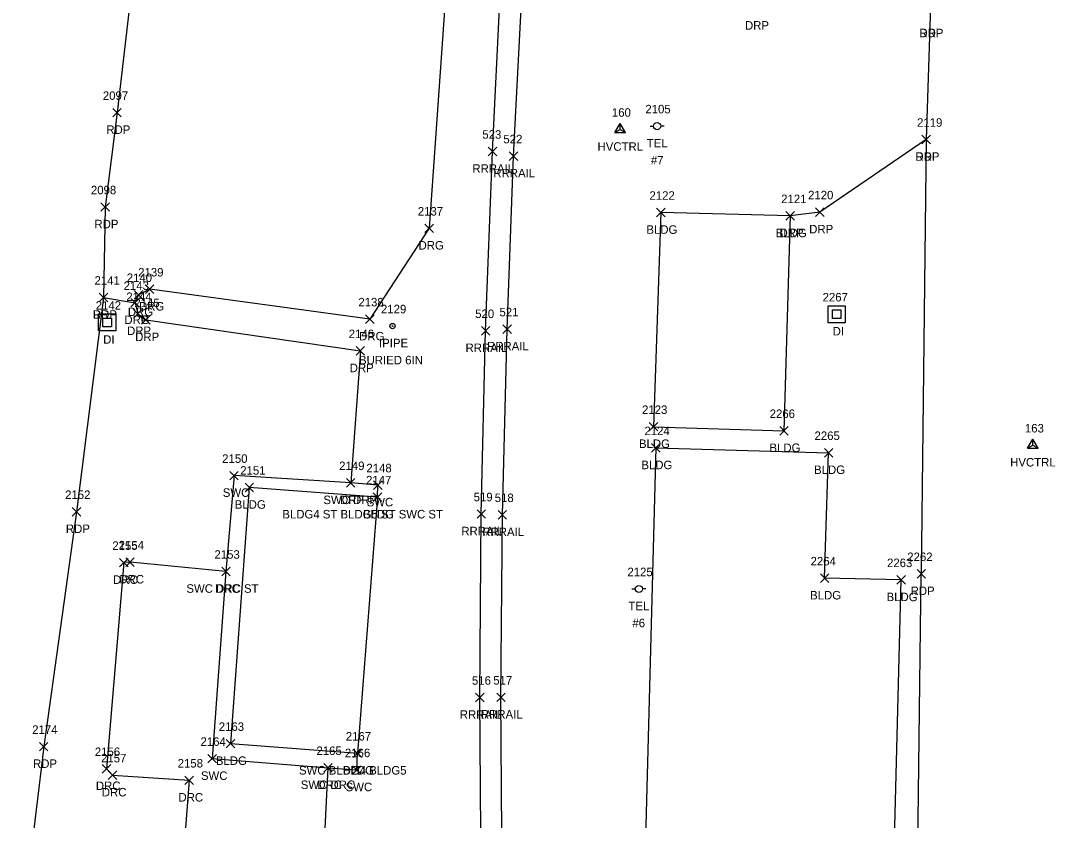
# Model space of a CAD drawing. Extents: x 1767353 to 1772625, y 740790 to 747702.
# Drawn here: x 1770045.2 to 1770288.3, y 741351 to 741538.9 of the extents above; entities that cross this region are included whole.
import ezdxf

# ---------------------------------------------------------------- set-up
doc = ezdxf.new("R2010")
doc.units = 0
for name, color, linetype in [('C_A', 7, 'Continuous'), ('C_I', 7, 'Continuous'), ('CPSM', 7, 'Continuous'), ('D_A', 7, 'Continuous'), ('D_I', 7, 'Continuous'), ('DS', 7, 'Continuous'), ('L_A', 7, 'Continuous'), ('L_I', 7, 'Continuous'), ('L_TIC', 7, 'Continuous'), ('LBC', 7, 'Continuous'), ('M_A', 7, 'Continuous'), ('M_C', 7, 'Continuous'), ('M_I', 7, 'Continuous'), ('MPIP', 7, 'Continuous'), ('P_A', 7, 'Continuous'), ('P_I', 7, 'Continuous'), ('P_TIC', 7, 'Continuous'), ('PET', 7, 'Continuous'), ('R_A', 7, 'Continuous'), ('R_I', 7, 'Continuous'), ('R_TIC', 7, 'Continuous'), ('RDG', 7, 'Continuous'), ('RDP', 7, 'Continuous'), ('RR', 7, 'Continuous'), ('RSW', 7, 'Continuous'), ('U_A', 7, 'Continuous'), ('U_C', 7, 'Continuous'), ('U_I', 7, 'Continuous'), ('UP', 7, 'Continuous')]:
    doc.layers.add(name, color=color, linetype=linetype)

msp = doc.modelspace()

# ---------------------------------------------------------------- linework, layer by layer
at = {"layer": 'CPSM'}
for p, q in [((1770184.78, 741512.6), (1770186.03, 741514.77)), ((1770184.78, 741512.6), (1770186.04, 741513.33)), ((1770187.28, 741512.6), (1770186.03, 741514.77)), ((1770186.04, 741513.33), (1770186.03, 741514.77)), ((1770186.04, 741513.33), (1770186.04, 741513.33)), ((1770186.04, 741513.33), (1770187.28, 741512.6)), ((1770184.78, 741512.6), (1770187.28, 741512.6)), ((1770281.75, 741438.4), (1770283, 741440.56)), ((1770284.25, 741438.4), (1770283, 741440.56)), ((1770283, 741439.12), (1770283, 741440.56)), ((1770281.75, 741438.4), (1770283, 741439.12)), ((1770281.75, 741438.4), (1770284.25, 741438.4)), ((1770283, 741439.12), (1770283, 741439.12)), ((1770283, 741439.12), (1770284.25, 741438.4))]:
    msp.add_line(p, q, dxfattribs=at)
at = {"layer": 'DS'}
for p, q in [((1770234.92, 741471.91), (1770238.92, 741471.91)), ((1770234.92, 741467.91), (1770234.92, 741471.91)), ((1770238.92, 741471.91), (1770238.92, 741467.91)), ((1770063.5, 741469.97), (1770067.5, 741469.97)), ((1770063.5, 741465.97), (1770063.5, 741469.97)), ((1770067.5, 741469.97), (1770067.5, 741465.97)), ((1770235.92, 741468.91), (1770235.92, 741470.91)), ((1770235.92, 741470.91), (1770237.92, 741470.91)), ((1770236.93, 741469.91), (1770236.93, 741469.91)), ((1770236.93, 741469.91), (1770236.93, 741469.91)), ((1770237.92, 741470.91), (1770237.92, 741468.91)), ((1770064.5, 741466.97), (1770064.5, 741468.97)), ((1770064.5, 741468.97), (1770066.5, 741468.97)), ((1770066.5, 741466.97), (1770064.5, 741466.97)), ((1770065.5, 741467.97), (1770065.5, 741467.97)), ((1770065.5, 741467.97), (1770065.5, 741467.97)), ((1770066.5, 741468.97), (1770066.5, 741466.97)), ((1770238.92, 741467.91), (1770234.92, 741467.91)), ((1770237.92, 741468.91), (1770235.92, 741468.91)), ((1770067.5, 741465.97), (1770063.5, 741465.97))]:
    msp.add_line(p, q, dxfattribs=at)
at = {"layer": 'L_TIC'}
for points in [[(1770194.62, 741492.81), (1770196.62, 741494.81)], [(1770196.62, 741492.81), (1770194.62, 741494.81)], [(1770225.01, 741492.02), (1770227.01, 741494.02)], [(1770227.01, 741492.02), (1770225.01, 741494.02)], [(1770225.01, 741492.02), (1770227.01, 741494.02)], [(1770227.01, 741492.02), (1770225.01, 741494.02)], [(1770192.88, 741442.47), (1770194.88, 741444.47)], [(1770194.88, 741442.47), (1770192.88, 741444.47)], [(1770223.54, 741441.52), (1770225.54, 741443.52)], [(1770225.54, 741441.52), (1770223.54, 741443.52)], [(1770223.54, 741441.52), (1770225.54, 741443.52)], [(1770225.54, 741441.52), (1770223.54, 741443.52)], [(1770193.44, 741437.49), (1770195.44, 741439.49)], [(1770195.44, 741437.49), (1770193.44, 741439.49)], [(1770193.44, 741437.49), (1770195.44, 741439.49)], [(1770195.44, 741437.49), (1770193.44, 741439.49)], [(1770234.03, 741436.35), (1770236.03, 741438.35)], [(1770236.03, 741436.35), (1770234.03, 741438.35)], [(1770234.03, 741436.35), (1770236.03, 741438.35)], [(1770236.03, 741436.35), (1770234.03, 741438.35)], [(1770097.89, 741428.19), (1770099.89, 741430.19)], [(1770099.89, 741428.19), (1770097.89, 741430.19)], [(1770128.02, 741425.91), (1770130.02, 741427.91)], [(1770130.02, 741425.91), (1770128.02, 741427.91)], [(1770128.02, 741425.91), (1770130.02, 741427.91)], [(1770130.02, 741425.91), (1770128.02, 741427.91)], [(1770233.09, 741406.87), (1770235.09, 741408.87)], [(1770235.09, 741406.87), (1770233.09, 741408.87)], [(1770251.07, 741406.47), (1770253.07, 741408.47)], [(1770253.07, 741406.47), (1770251.07, 741408.47)], [(1770093.46, 741367.98), (1770095.46, 741369.98)], [(1770095.46, 741367.98), (1770093.46, 741369.98)], [(1770123.31, 741365.71), (1770125.31, 741367.71)], [(1770125.31, 741365.71), (1770123.31, 741367.71)], [(1770123.31, 741365.71), (1770125.31, 741367.71)], [(1770125.31, 741365.71), (1770123.31, 741367.71)]]:
    msp.add_lwpolyline(points, dxfattribs=at)
at = {"layer": 'LBC'}
for points in [[(1770226.01, 741493.02), (1770195.62, 741493.81), (1770193.88, 741443.47), (1770224.54, 741442.52)], [(1770226.01, 741493.02), (1770224.54, 741442.52)], [(1770194.44, 741438.49), (1770191.02, 741308.31), (1770207.19, 741307.57), (1770249.47, 741306.66), (1770252.07, 741407.47), (1770234.09, 741407.87), (1770235.03, 741437.35)], [(1770194.44, 741438.49), (1770235.03, 741437.35)], [(1770129.02, 741426.91), (1770098.89, 741429.19), (1770094.46, 741368.98), (1770124.31, 741366.71)], [(1770129.02, 741426.91), (1770124.31, 741366.71)]]:
    msp.add_lwpolyline(points, dxfattribs=at)
at = {"layer": 'MPIP'}
for radius in [0.625, 0.0833]:
    msp.add_circle((1770132.54, 741467.13), radius, dxfattribs=at)
at = {"layer": 'P_TIC'}
for points in [[(1770066.82, 741516.29), (1770068.82, 741518.29)], [(1770068.82, 741516.29), (1770066.82, 741518.29)], [(1770256.94, 741509.97), (1770258.94, 741511.97)], [(1770258.94, 741509.97), (1770256.94, 741511.97)], [(1770064.02, 741494.1), (1770066.02, 741496.1)], [(1770066.02, 741494.1), (1770064.02, 741496.1)], [(1770063.65, 741472.85), (1770065.65, 741474.85)], [(1770065.65, 741472.85), (1770063.65, 741474.85)], [(1770057.3, 741422.48), (1770059.3, 741424.48)], [(1770059.3, 741422.48), (1770057.3, 741424.48)], [(1770255.82, 741407.89), (1770257.82, 741409.89)], [(1770257.82, 741407.89), (1770255.82, 741409.89)], [(1770255.82, 741407.89), (1770257.82, 741409.89)], [(1770257.82, 741407.89), (1770255.82, 741409.89)], [(1770049.58, 741367.28), (1770051.58, 741369.28)], [(1770051.58, 741367.28), (1770049.58, 741369.28)]]:
    msp.add_lwpolyline(points, dxfattribs=at)
at = {"layer": 'PET'}
for points in [[(1770086.36, 741896.23), (1770087.49, 741787.65), (1770087.53, 741783.15), (1770087.13, 741775.79), (1770085.91, 741755.24), (1770081.77, 741704.72), (1770080.78, 741668.58), (1770077.45, 741606.56), (1770073.71, 741567.99), (1770067.82, 741517.29), (1770065.02, 741495.1), (1770064.65, 741473.85), (1770058.3, 741423.48), (1770050.58, 741368.28), (1770045.18, 741323.67)], [(1770259.69, 741610.34), (1770259.04, 741577.82), (1770258.88, 741540.01), (1770257.94, 741510.97), (1770256.82, 741408.89)], [(1770255.54, 741305.89), (1770256.82, 741408.89)]]:
    msp.add_lwpolyline(points, dxfattribs=at)
at = {"layer": 'R_TIC'}
for points in [[(1770256.94, 741509.97), (1770258.94, 741511.97)], [(1770258.94, 741509.97), (1770256.94, 741511.97)], [(1770155.03, 741507.16), (1770157.03, 741509.16)], [(1770157.03, 741507.16), (1770155.03, 741509.16)], [(1770159.97, 741506.07), (1770161.97, 741508.07)], [(1770161.97, 741506.07), (1770159.97, 741508.07)], [(1770225.01, 741492.02), (1770227.01, 741494.02)], [(1770227.01, 741492.02), (1770225.01, 741494.02)], [(1770231.98, 741492.91), (1770233.98, 741494.91)], [(1770233.98, 741492.91), (1770231.98, 741494.91)], [(1770140.18, 741489.11), (1770142.18, 741491.11)], [(1770142.18, 741489.11), (1770140.18, 741491.11)], [(1770074.49, 741474.78), (1770076.49, 741476.78)], [(1770076.49, 741474.78), (1770074.49, 741476.78)], [(1770063.65, 741472.85), (1770065.65, 741474.85)], [(1770065.65, 741472.85), (1770063.65, 741474.85)], [(1770071.87, 741473.48), (1770073.87, 741475.48)], [(1770073.87, 741473.48), (1770071.87, 741475.48)], [(1770071.05, 741471.61), (1770073.05, 741473.61)], [(1770073.05, 741471.61), (1770071.05, 741473.61)], [(1770071.05, 741471.61), (1770073.05, 741473.61)], [(1770073.05, 741471.61), (1770071.05, 741473.61)], [(1770071.68, 741469.01), (1770073.68, 741471.01)], [(1770073.68, 741469.01), (1770071.68, 741471.01)], [(1770073.59, 741467.58), (1770075.59, 741469.58)], [(1770075.59, 741467.58), (1770073.59, 741469.58)], [(1770126.23, 741467.75), (1770128.23, 741469.75)], [(1770128.23, 741467.75), (1770126.23, 741469.75)], [(1770153.43, 741465.02), (1770155.43, 741467.02)], [(1770155.43, 741465.02), (1770153.43, 741467.02)], [(1770158.48, 741465.41), (1770160.48, 741467.41)], [(1770160.48, 741465.41), (1770158.48, 741467.41)], [(1770124, 741460.29), (1770126, 741462.29)], [(1770126, 741460.29), (1770124, 741462.29)], [(1770094.31, 741430.98), (1770096.31, 741432.98)], [(1770096.31, 741430.98), (1770094.31, 741432.98)], [(1770121.72, 741429.28), (1770123.72, 741431.28)], [(1770123.72, 741429.28), (1770121.72, 741431.28)], [(1770121.72, 741429.28), (1770123.72, 741431.28)], [(1770123.72, 741429.28), (1770121.72, 741431.28)], [(1770128.11, 741428.75), (1770130.11, 741430.75)], [(1770130.11, 741428.75), (1770128.11, 741430.75)], [(1770128.02, 741425.91), (1770130.02, 741427.91)], [(1770130.02, 741425.91), (1770128.02, 741427.91)], [(1770152.42, 741421.94), (1770154.42, 741423.94)], [(1770154.42, 741421.94), (1770152.42, 741423.94)], [(1770157.37, 741421.76), (1770159.37, 741423.76)], [(1770159.37, 741421.76), (1770157.37, 741423.76)], [(1770068.4, 741410.52), (1770070.4, 741412.52)], [(1770070.4, 741410.52), (1770068.4, 741412.52)], [(1770069.88, 741410.63), (1770071.88, 741412.63)], [(1770071.88, 741410.63), (1770069.88, 741412.63)], [(1770092.41, 741408.44), (1770094.41, 741410.44)], [(1770094.41, 741408.44), (1770092.41, 741410.44)], [(1770092.41, 741408.44), (1770094.41, 741410.44)], [(1770094.41, 741408.44), (1770092.41, 741410.44)], [(1770152.07, 741378.82), (1770154.07, 741380.82)], [(1770154.07, 741378.82), (1770152.07, 741380.82)], [(1770157.03, 741378.87), (1770159.03, 741380.87)], [(1770159.03, 741378.87), (1770157.03, 741380.87)], [(1770123.31, 741365.71), (1770125.31, 741367.71)], [(1770125.31, 741365.71), (1770123.31, 741367.71)], [(1770089.17, 741364.46), (1770091.17, 741366.46)], [(1770091.17, 741364.46), (1770089.17, 741366.46)], [(1770064.35, 741362.07), (1770066.35, 741364.07)], [(1770066.35, 741362.07), (1770064.35, 741364.07)], [(1770065.76, 741360.57), (1770067.76, 741362.57)], [(1770067.76, 741360.57), (1770065.76, 741362.57)], [(1770116.41, 741362.31), (1770118.41, 741364.31)], [(1770118.41, 741362.31), (1770116.41, 741364.31)], [(1770116.41, 741362.31), (1770118.41, 741364.31)], [(1770118.41, 741362.31), (1770116.41, 741364.31)], [(1770123.17, 741361.8), (1770125.17, 741363.8)], [(1770125.17, 741361.8), (1770123.17, 741363.8)], [(1770083.76, 741359.37), (1770085.76, 741361.37)], [(1770085.76, 741359.37), (1770083.76, 741361.37)]]:
    msp.add_lwpolyline(points, dxfattribs=at)
at = {"layer": 'RDG'}
msp.add_lwpolyline([(1770133.81, 741561.26), (1770145.92, 741558.06), (1770141.18, 741490.11), (1770127.23, 741468.75), (1770075.49, 741475.78), (1770072.87, 741474.48), (1770072.05, 741472.61)], dxfattribs=at)
at = {"layer": 'RDP'}
for points in [[(1770257.94, 741510.97), (1770232.98, 741493.91), (1770226.01, 741493.02)], [(1770064.65, 741473.85), (1770072.05, 741472.61), (1770072.68, 741470.01), (1770074.59, 741468.58), (1770125, 741461.29), (1770122.72, 741430.28)], [(1770093.41, 741409.44), (1770070.88, 741411.63), (1770069.4, 741411.52), (1770065.35, 741363.07), (1770066.76, 741361.57), (1770084.76, 741360.37), (1770082.95, 741336.98), (1770084.22, 741335.12), (1770115.82, 741330.18), (1770117.41, 741363.31)]]:
    msp.add_lwpolyline(points, dxfattribs=at)
at = {"layer": 'RR'}
for points in [[(1770158.18, 741192.17), (1770156.33, 741234.55), (1770154.66, 741279.77), (1770153.5, 741326.69), (1770153.07, 741379.82), (1770153.42, 741422.94), (1770154.43, 741466.02), (1770156.03, 741508.16), (1770157.87, 741545.07), (1770160.69, 741586.39), (1770163.59, 741622.82), (1770166.84, 741658.9), (1770171.01, 741697.88), (1770175.49, 741734.8), (1770180.59, 741775.05), (1770185.91, 741810.5), (1770192.47, 741851.32), (1770197.89, 741882.78), (1770201.13, 741901.96), (1770208.66, 741941.8), (1770211.54, 741956.24), (1770217.02, 741983.21), (1770222.11, 742006.18)], [(1770163.08, 741192.31), (1770161.21, 741234.64), (1770159.62, 741280.6), (1770158.4, 741326.37), (1770158.03, 741379.87), (1770158.37, 741422.76), (1770159.48, 741466.41), (1770160.97, 741507.07), (1770162.92, 741544.79), (1770165.6, 741585.33), (1770168.59, 741623.26), (1770171.89, 741657.97), (1770175.98, 741697.29), (1770180.38, 741733.87), (1770185.58, 741774.59), (1770190.55, 741808.84), (1770197.31, 741850.84), (1770202.43, 741880.83), (1770205.99, 741900.79), (1770213.55, 741940.61), (1770216.39, 741955.4), (1770221.78, 741982.04), (1770226.9, 742005.14)]]:
    msp.add_lwpolyline(points, dxfattribs=at)
at = {"layer": 'RSW'}
msp.add_lwpolyline([(1770129.02, 741426.91), (1770129.11, 741429.75), (1770122.72, 741430.28), (1770095.31, 741431.98), (1770093.41, 741409.44), (1770090.17, 741365.46), (1770117.41, 741363.31), (1770124.17, 741362.8), (1770124.31, 741366.71)], dxfattribs=at)
at = {"layer": 'UP'}
for p, q in [((1770193.08, 741514.12), (1770193.9, 741514.12)), ((1770194.74, 741514.12), (1770194.74, 741514.12)), ((1770196.4, 741514.12), (1770195.57, 741514.12)), ((1770195.57, 741514.12), (1770195.57, 741514.12)), ((1770196.4, 741514.12), (1770196.4, 741514.12)), ((1770188.79, 741405.33), (1770189.61, 741405.33)), ((1770190.45, 741405.34), (1770190.45, 741405.34)), ((1770192.11, 741405.34), (1770191.28, 741405.34)), ((1770191.28, 741405.34), (1770191.28, 741405.34)), ((1770192.11, 741405.34), (1770192.11, 741405.34))]:
    msp.add_line(p, q, dxfattribs=at)
for centre in [(1770194.74, 741514.12), (1770190.45, 741405.34)]:
    msp.add_circle(centre, 0.833, dxfattribs=at)

# ---------------------------------------------------------------- texts
at = {"layer": 'C_A'}
for p in [(1770180.73, 741508.33), (1770277.7, 741434.12)]:
    msp.add_text('HVCTRL', height=2, dxfattribs=at).set_placement(p)
at = {"layer": 'C_I'}
for s, p in [('160', (1770184.11, 741516.33)), ('163', (1770281.16, 741442.12))]:
    msp.add_text(s, height=2, dxfattribs=at).set_placement(p)
at = {"layer": 'D_A'}
for p in [(1770235.98, 741464.91), (1770064.56, 741462.97)]:
    msp.add_text('DI', height=2, dxfattribs=at).set_placement(p)
at = {"layer": 'D_I'}
for s, p in [('2267', (1770233.62, 741472.91)), ('2142', (1770062.81, 741470.97))]:
    msp.add_text(s, height=2, dxfattribs=at).set_placement(p)
at = {"layer": 'L_A'}
for p in [(1770192.21, 741488.81), (1770222.61, 741488.02), (1770222.61, 741488.02), (1770190.47, 741438.47), (1770221.13, 741437.52), (1770221.13, 741437.52), (1770191.03, 741433.49), (1770191.03, 741433.49), (1770231.62, 741432.35), (1770231.62, 741432.35), (1770095.48, 741424.19), (1770125.61, 741421.91), (1770125.61, 741421.91), (1770230.68, 741402.87), (1770248.66, 741402.47), (1770091.05, 741363.98), (1770120.91, 741361.71), (1770120.91, 741361.71)]:
    msp.add_text('BLDG', height=2, dxfattribs=at).set_placement(p)
at = {"layer": 'L_I'}
for s, p in [('2122', (1770192.93, 741496.81)), ('2121', (1770223.89, 741496.02)), ('2121', (1770223.89, 741496.02)), ('2123', (1770191.19, 741446.47)), ('2266', (1770221.18, 741445.52)), ('2266', (1770221.18, 741445.52)), ('2124', (1770191.75, 741441.49)), ('2124', (1770191.75, 741441.49)), ('2265', (1770231.72, 741440.35)), ('2265', (1770231.72, 741440.35)), ('2151', (1770096.77, 741432.19)), ('2147', (1770126.33, 741429.91)), ('2147', (1770126.33, 741429.91)), ('2264', (1770230.79, 741410.87)), ('2263', (1770248.76, 741410.47)), ('2163', (1770091.72, 741371.98)), ('2167', (1770121.57, 741369.71)), ('2167', (1770121.57, 741369.71))]:
    msp.add_text(s, height=2, dxfattribs=at).set_placement(p)
at = {"layer": 'M_A'}
msp.add_text('IPIPE', height=2, dxfattribs=at).set_placement((1770129.38, 741462.13))
at = {"layer": 'M_C'}
msp.add_text('BURIED 6IN', height=2, dxfattribs=at).set_placement((1770124.68, 741458.13))
at = {"layer": 'M_I'}
msp.add_text('2129', height=2, dxfattribs=at).set_placement((1770129.84, 741470.13))
at = {"layer": 'P_A'}
for p in [(1770256.36, 741535.01), (1770065.3, 741512.29), (1770255.43, 741505.97), (1770062.51, 741490.1), (1770062.14, 741468.85), (1770055.79, 741418.48), (1770254.31, 741403.89), (1770254.31, 741403.89), (1770048.07, 741363.28)]:
    msp.add_text('RDP', height=2, dxfattribs=at).set_placement(p)
at = {"layer": 'P_I'}
for s, p in [('2097', (1770064.48, 741520.29)), ('2119', (1770255.81, 741513.97)), ('2098', (1770061.68, 741498.1)), ('2141', (1770062.53, 741476.85)), ('2152', (1770055.61, 741426.48)), ('2262', (1770253.51, 741411.89)), ('2262', (1770253.51, 741411.89)), ('2174', (1770047.89, 741371.28))]:
    msp.add_text(s, height=2, dxfattribs=at).set_placement(p)
at = {"layer": 'R_A'}
for s, p in [('DRP', (1770215.38, 741536.8)), ('DRP', (1770256.36, 741535.01)), ('DRP', (1770255.43, 741505.97)), ('RRRAIL', (1770151.32, 741503.16)), ('RRRAIL', (1770156.26, 741502.07)), ('DRP', (1770223.5, 741488.02)), ('DRP', (1770230.47, 741488.91)), ('DRG', (1770138.67, 741485.11)), ('DRG', (1770072.98, 741470.78)), ('DRP', (1770062.14, 741468.85)), ('DRG', (1770069.54, 741467.61)), ('DRP', (1770069.54, 741467.61)), ('DRG', (1770070.36, 741469.48)), ('DRP', (1770070.17, 741465.01)), ('DRP', (1770072.08, 741463.58)), ('DRG', (1770124.71, 741463.75)), ('RRRAIL', (1770149.72, 741461.02)), ('RRRAIL', (1770154.77, 741461.41)), ('DRP', (1770122.49, 741456.29)), ('SWC', (1770092.67, 741426.98)), ('SWC DRP', (1770116.3, 741425.28)), ('DRP', (1770120.21, 741425.28)), ('SWC', (1770126.47, 741424.75)), ('BLDG4 ST BLDG5 ST SWC ST', (1770106.66, 741421.91)), ('RRRAIL', (1770148.72, 741417.94)), ('RRRAIL', (1770153.66, 741417.76)), ('DRC', (1770066.89, 741406.52)), ('DRC', (1770068.37, 741406.63)), ('SWC DRC ST', (1770084.12, 741404.44)), ('DRC', (1770090.89, 741404.44)), ('RRRAIL', (1770148.36, 741374.82)), ('RRRAIL', (1770153.32, 741374.87)), ('SWC', (1770087.53, 741360.46)), ('SWC BLDG4 BLDG5', (1770110.58, 741361.71)), ('DRC', (1770062.84, 741358.07)), ('SWC DRC', (1770110.99, 741358.31)), ('DRC', (1770114.89, 741358.31)), ('DRC', (1770064.24, 741356.57)), ('SWC', (1770121.53, 741357.8)), ('DRC', (1770082.25, 741355.37))]:
    msp.add_text(s, height=2, dxfattribs=at).set_placement(p)
at = {"layer": 'R_I'}
for s, p in [('2119', (1770255.81, 741513.97)), ('523', (1770153.66, 741511.16)), ('522', (1770158.6, 741510.07)), ('2120', (1770230.2, 741496.91)), ('2121', (1770223.89, 741496.02)), ('2137', (1770138.49, 741493.11)), ('2140', (1770070.09, 741477.48)), ('2139', (1770072.79, 741478.78)), ('2141', (1770062.53, 741476.85)), ('2143', (1770069.36, 741475.61)), ('2143', (1770069.36, 741475.61)), ('2144', (1770069.99, 741473.01)), ('2145', (1770071.89, 741471.58)), ('2138', (1770124.53, 741471.75)), ('520', (1770151.98, 741469.02)), ('521', (1770157.68, 741469.41)), ('2146', (1770122.25, 741464.29)), ('2150', (1770092.53, 741434.98)), ('2149', (1770120.02, 741433.28)), ('2149', (1770120.02, 741433.28)), ('2148', (1770126.41, 741432.75)), ('2147', (1770126.33, 741429.91)), ('519', (1770151.62, 741425.94)), ('518', (1770156.57, 741425.76)), ('2155', (1770066.71, 741414.52)), ('2154', (1770068.19, 741414.63)), ('2153', (1770090.71, 741412.44)), ('2153', (1770090.71, 741412.44)), ('516', (1770151.22, 741382.82)), ('517', (1770156.23, 741382.87)), ('2164', (1770087.43, 741368.46)), ('2167', (1770121.57, 741369.71)), ('2156', (1770062.6, 741366.07)), ('2165', (1770114.67, 741366.31)), ('2165', (1770114.67, 741366.31)), ('2166', (1770121.37, 741365.8)), ('2157', (1770064.06, 741364.57)), ('2158', (1770082.07, 741363.37))]:
    msp.add_text(s, height=2, dxfattribs=at).set_placement(p)
at = {"layer": 'U_A'}
for p in [(1770192.3, 741509.12), (1770188, 741400.34)]:
    msp.add_text('TEL', height=2, dxfattribs=at).set_placement(p)
at = {"layer": 'U_C'}
for s, p in [('#7', (1770193.27, 741505.12)), ('#6', (1770188.93, 741396.34))]:
    msp.add_text(s, height=2, dxfattribs=at).set_placement(p)
at = {"layer": 'U_I'}
for s, p in [('2105', (1770191.97, 741517.12)), ('2125', (1770187.75, 741408.34))]:
    msp.add_text(s, height=2, dxfattribs=at).set_placement(p)

doc.saveas('drawing.dxf')
